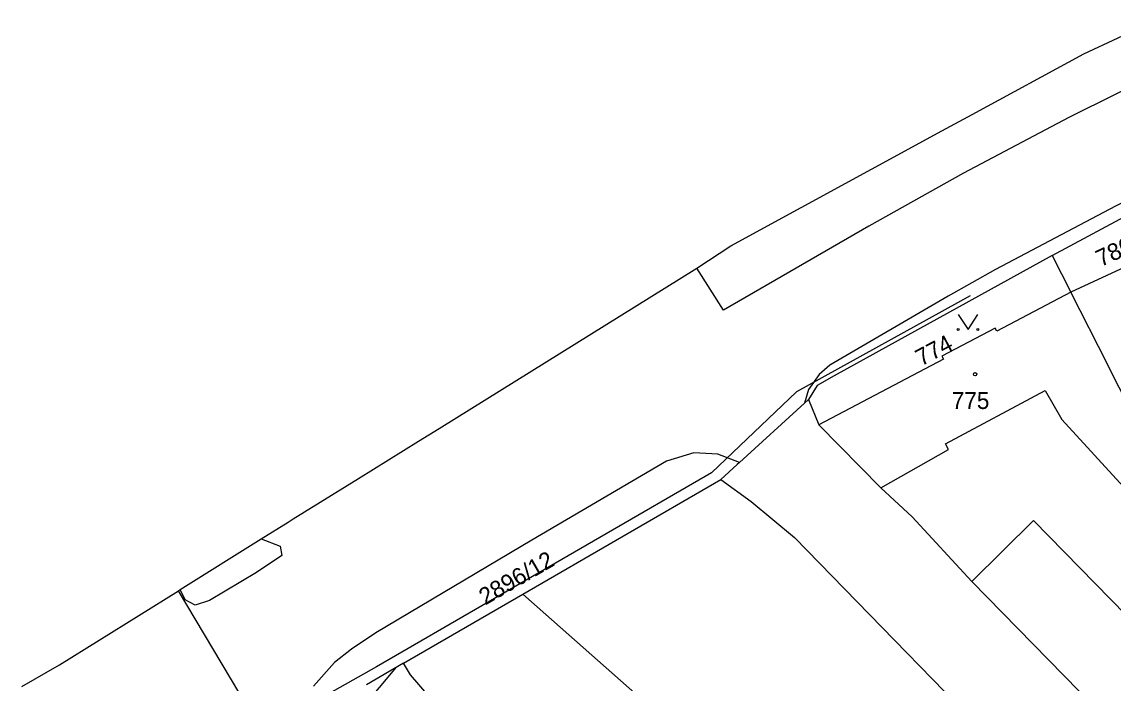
# Model space of a CAD drawing. Extents: x -496682 to -495776, y -1088797 to -1088018.
# Drawn here: x -496609.5 to -496499.5, y -1088086.1 to -1088019.5 of the extents above; entities that cross this region are included whole.
import ezdxf

# ---------------------------------------------------------------- set-up
doc = ezdxf.new("R2010")
doc.units = 0
for name, color, linetype in [('Hranice parcel', 7, 'Continuous'), ('Parcelní čísla', 7, 'Continuous'), ('Vnitřní kresba', 7, 'Continuous'), ('Vrstva 20', 7, 'Continuous'), ('Značky budov', 7, 'Continuous'), ('Značky kultur', 7, 'Continuous')]:
    doc.layers.add(name, color=color, linetype=linetype)

msp = doc.modelspace()

# ---------------------------------------------------------------- linework, layer by layer
at = {"layer": 'Hranice parcel'}
for p, q in [((-496505.64, -1088043.04), (-496491.56, -1088035.46)), ((-496541.46, -1088044.3), (-496538.04, -1088042.05)), ((-496505.64, -1088043.04), (-496503.75, -1088046.73)), ((-496567.44, -1088060.46), (-496541.46, -1088044.3)), ((-496530.21, -1088056.55), (-496530.6, -1088057.93)), ((-496529.32, -1088056.14), (-496530.18, -1088057.55)), ((-496530.6, -1088057.93), (-496537.16, -1088063.89)), ((-496530.18, -1088057.55), (-496530.6, -1088057.93)), ((-496530.18, -1088057.55), (-496529.16, -1088060.1)), ((-496537.16, -1088063.89), (-496539.32, -1088063.04)), ((-496582.16, -1088069.58), (-496575.56, -1088065.49)), ((-496559, -1088077.16), (-496539.03, -1088065.6)), ((-496584.7, -1088091.9), (-496593.73, -1088076.81)), ((-496571.02, -1088084.13), (-496559, -1088077.16)), ((-496571.02, -1088084.13), (-496574.77, -1088086.3))]:
    msp.add_line(p, q, dxfattribs=at)
for points in [[(-496483.48, -1088019.49), (-496485.82, -1088020.47), (-496494.39, -1088024.4), (-496503.94, -1088029.11), (-496514.57, -1088034.74), (-496524.1, -1088040.06), (-496538.76, -1088048.54), (-496541.46, -1088044.3)], [(-496538.04, -1088042.05), (-496516.74, -1088030.48), (-496513.69, -1088028.82), (-496502.45, -1088022.72), (-496495.5, -1088019.49)], [(-496455.71, -1088019.49), (-496458.68, -1088020.53), (-496462.8, -1088022.03), (-496471.09, -1088025.21), (-496477.17, -1088027.68), (-496482.67, -1088030.05), (-496486.45, -1088031.8), (-496489.58, -1088033.31), (-496492.04, -1088034.49), (-496499.24, -1088038.05), (-496511.35, -1088044.46), (-496516.12, -1088047.12), (-496528.03, -1088054.1), (-496529.12, -1088055.01), (-496530.21, -1088056.55)], [(-496489.76, -1088040.29), (-496494.55, -1088042.49), (-496494.62, -1088042.28), (-496495.28, -1088042.59), (-496495.68, -1088041.71), (-496498.16, -1088042.85), (-496497.76, -1088043.73), (-496498.39, -1088044.02), (-496498.3, -1088044.22), (-496503.75, -1088046.73)], [(-496505.64, -1088043.04), (-496527.61, -1088055.16), (-496529.32, -1088056.14)], [(-496503.75, -1088046.73), (-496511.2, -1088050.65), (-496511.36, -1088050.35), (-496516.74, -1088053.18), (-496516.58, -1088053.48), (-496529.16, -1088060.1)], [(-496485.62, -1088071.37), (-496496.9, -1088058.96), (-496497.43, -1088059.17), (-496499.6, -1088054.9), (-496500.03, -1088054.06), (-496503.75, -1088046.73)], [(-496529.16, -1088060.1), (-496522.91, -1088066.43), (-496519.74, -1088069.36), (-496513.72, -1088075.89), (-496502.91, -1088086.95), (-496490.59, -1088099.54)], [(-496575.56, -1088065.49), (-496569.52, -1088061.75), (-496567.44, -1088060.46)], [(-496539.32, -1088063.04), (-496541.74, -1088062.93), (-496544.5, -1088063.75), (-496558.08, -1088071.73), (-496573.82, -1088081.05), (-496576.28, -1088082.69), (-496577.99, -1088084.05), (-496580.1, -1088086.44)], [(-496537.16, -1088063.89), (-496537.4, -1088064.11), (-496539.03, -1088065.6)], [(-496539.03, -1088065.6), (-496535.97, -1088067.83), (-496531.62, -1088071.46), (-496507.63, -1088096.03), (-496473.26, -1088131.47)], [(-496585.38, -1088071.6), (-496582.67, -1088069.91), (-496582.16, -1088069.58)], [(-496593.73, -1088076.81), (-496593.53, -1088076.68), (-496585.38, -1088071.6)], [(-496609.51, -1088086.48), (-496605.72, -1088084.28), (-496593.73, -1088076.81)], [(-496559, -1088077.16), (-496484.87, -1088142.67), (-496473.26, -1088131.47)], [(-496449.81, -1088155.53), (-496454.1, -1088151.6), (-496460.56, -1088145.42), (-496469.27, -1088136.13), (-496476.41, -1088144.48), (-496483.29, -1088152.42), (-496496.71, -1088143.01), (-496497.27, -1088143.67), (-496509.81, -1088132.58), (-496512.72, -1088135.39), (-496534.24, -1088116.3), (-496558.95, -1088090.57), (-496566.25, -1088088.69), (-496568.44, -1088087.46), (-496570.32, -1088085.3), (-496571.02, -1088084.13)]]:
    msp.add_lwpolyline(points, dxfattribs=at)
at = {"layer": 'Vnitřní kresba'}
for p, q in [((-496516.39, -1088062), (-496506.32, -1088056.65)), ((-496516.07, -1088062.57), (-496516.39, -1088062)), ((-496522.91, -1088066.43), (-496516.07, -1088062.57)), ((-496585.38, -1088071.6), (-496583.46, -1088072.32)), ((-496583.31, -1088073.28), (-496585.85, -1088074.98)), ((-496583.46, -1088072.32), (-496583.31, -1088073.28)), ((-496585.85, -1088074.98), (-496590.58, -1088077.79)), ((-496593.03, -1088077.74), (-496593.53, -1088076.68)), ((-496592.02, -1088078.26), (-496593.03, -1088077.74)), ((-496590.58, -1088077.79), (-496592.02, -1088078.26))]:
    msp.add_line(p, q, dxfattribs=at)
for points in [[(-496513.9, -1088047.1), (-496531.42, -1088056.78), (-496539.98, -1088064.95), (-496573.76, -1088084.47), (-496608.65, -1088104.15)], [(-496506.32, -1088056.65), (-496504.65, -1088059.56), (-496498.05, -1088066.76)], [(-496513.72, -1088075.89), (-496507.5, -1088069.73), (-496496.62, -1088080.87), (-496493.33, -1088078.18)]]:
    msp.add_lwpolyline(points, dxfattribs=at)
at = {"layer": 'Vrstva 20'}
msp.add_line((-496576.73, -1088090.48), (-496571.73, -1088084.52), dxfattribs=at)
at = {"layer": 'Značky budov'}
msp.add_circle((-496513.4, -1088055), 0.175, dxfattribs=at)
at = {"layer": 'Značky kultur'}
msp.add_lwpolyline([(-496515.11, -1088048.99), (-496514.11, -1088050.49), (-496513.11, -1088048.99)], dxfattribs=at)
for centre in [(-496515.11, -1088050.49), (-496513.11, -1088050.49)]:
    msp.add_circle(centre, 0.1, dxfattribs=at)

# ---------------------------------------------------------------- texts
at = {"layer": 'Parcelní čísla'}
for s, rotation, p in [('780', 25, (-496500.72, -1088044.21)), ('774', 28, (-496518.83, -1088054.22)), ('2896/12', 30, (-496562.79, -1088078.31))]:
    msp.add_text(s, height=1.7, rotation=rotation, dxfattribs=at).set_placement(p)
msp.add_text('775', height=1.7, dxfattribs=at).set_placement((-496515.75, -1088058.5))

doc.saveas('drawing.dxf')
